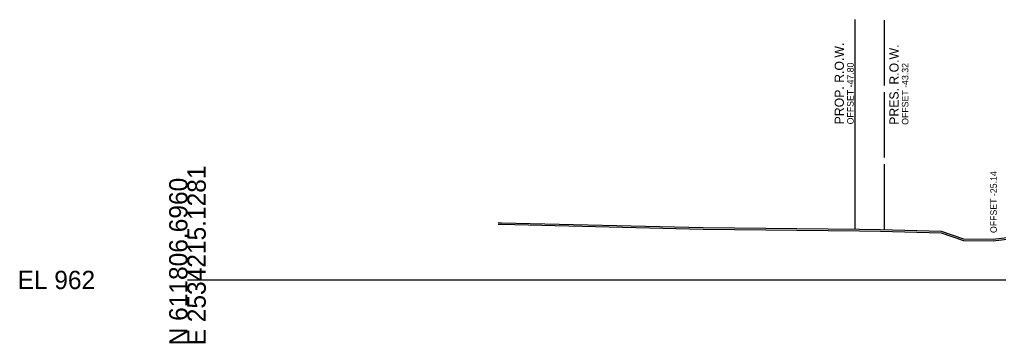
# Model space of a CAD drawing. Extents: x -192 to 2669, y -25 to 8040.
# Drawn here: x -25.7 to 124.1, y 4490.3 to 4539.8 of the extents above; entities that cross this region are included whole.
import ezdxf

# ---------------------------------------------------------------- set-up
doc = ezdxf.new("R2010")
doc.units = 0
for name, color, linetype in [('DESIGN - ROW - Right-of-Way and Easement Labels', 7, 'Continuous'), ('DESIGN - ROW - Right-of-Way Linework', 7, 'Continuous'), ('DESIGN - SHEET - Light Grid', 7, 'Continuous'), ('DESIGN - TYPICAL - Slope Tie Text', 7, 'Continuous'), ('SURVEY - GROUND - Bottom of Topsoil Layer', 7, 'Continuous'), ('SURVEY - GROUND - Top of Ground', 7, 'Continuous'), ('SURVEY - PROPERTY - ROW Lines', 7, 'Continuous'), ('SURVEY - PROPERTY - ROW Lines Text', 7, 'Continuous')]:
    doc.layers.add(name, color=color, linetype=linetype)

msp = doc.modelspace()

# ---------------------------------------------------------------- linework, layer by layer
at = {"layer": 'DESIGN - ROW - Right-of-Way Linework'}
msp.add_line((102.2, 4507.77), (102.2, 4539.77), dxfattribs=at)
at = {"layer": 'DESIGN - SHEET - Light Grid'}
msp.add_line((0, 4500), (150, 4500), dxfattribs=at)
at = {"layer": 'SURVEY - GROUND - Bottom of Topsoil Layer'}
for p, q in [((47.54, 4508.51), (48.05, 4508.5)), ((48.05, 4508.5), (78.94, 4507.75)), ((78.94, 4507.75), (102.84, 4507.52)), ((102.84, 4507.52), (106.08, 4507.47)), ((106.08, 4507.47), (115.34, 4507.19)), ((115.34, 4507.19), (118.77, 4506.03)), ((118.77, 4506.03), (123.29, 4505.99)), ((123.29, 4505.99), (128.38, 4506.58))]:
    msp.add_line(p, q, dxfattribs=at)
at = {"layer": 'SURVEY - GROUND - Top of Ground'}
msp.add_lwpolyline([(47.54, 4508.76), (48.05, 4508.75), (78.94, 4508), (102.84, 4507.77), (106.08, 4507.72), (115.34, 4507.44), (118.77, 4506.28), (123.29, 4506.24), (128.38, 4506.83)], dxfattribs=at)
at = {"layer": 'SURVEY - PROPERTY - ROW Lines'}
for p, q in [((106.68, 4529.7), (106.68, 4539.7)), ((106.68, 4518.7), (106.68, 4528.7)), ((106.68, 4507.7), (106.68, 4517.7))]:
    msp.add_line(p, q, dxfattribs=at)

# ---------------------------------------------------------------- texts
at = {"layer": 'DESIGN - ROW - Right-of-Way and Easement Labels'}
for s, height, p in [('PROP. R.O.W.', 1.4, (100.45, 4523.77)), ('OFFSET -47.80', 1, (101.95, 4523.77))]:
    msp.add_text(s, height=height, rotation=90, dxfattribs=at).set_placement(p)
at = {"layer": 'DESIGN - SHEET - Light Grid'}
for s, p in [('E 2534215.1281', (2.8, 4490)), ('N 611806.6960', (0, 4490))]:
    msp.add_text(s, height=2.8, rotation=90, dxfattribs=at).set_placement(p)
msp.add_text('EL 962', height=2.8, dxfattribs=at).set_placement((-26, 4498.6))
at = {"layer": 'DESIGN - TYPICAL - Slope Tie Text'}
msp.add_text('OFFSET -25.14', height=1, rotation=90, dxfattribs=at).set_placement((123.86, 4507.17))
at = {"layer": 'SURVEY - PROPERTY - ROW Lines Text'}
for s, height, p in [('PRES. R.O.W.', 1.4, (108.83, 4523.7)), ('OFFSET -43.32', 1, (110.33, 4523.7))]:
    msp.add_text(s, height=height, rotation=90, dxfattribs=at).set_placement(p)

doc.saveas('drawing.dxf')
